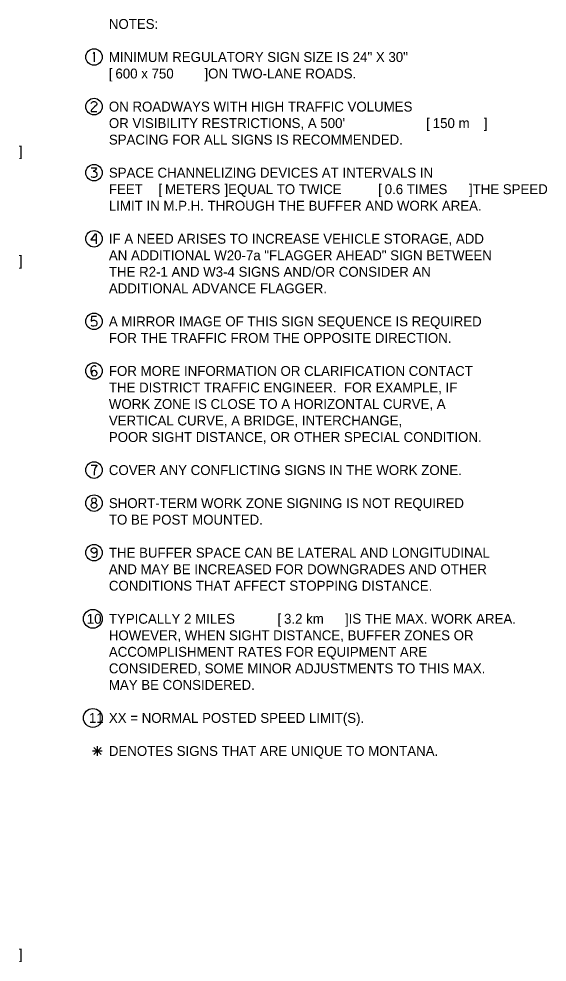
# Model space of a CAD drawing. Extents: x 49987.3 to 50021, y 49987.6 to 50011.4.
# Drawn here: x 49991.71 to 49994.9, y 50004.83 to 50010.54 of the extents above; entities that cross this region are included whole.
import ezdxf

# ---------------------------------------------------------------- set-up
doc = ezdxf.new("R2010")
doc.units = 0
doc.layers.add('Level 2', color=7, linetype='Continuous')

msp = doc.modelspace()

# ---------------------------------------------------------------- linework, layer by layer
at = {"layer": 'Level 2'}
for p, q in [((49992.1617, 50010.3362), (49992.1558, 50010.3258)), ((49992.1617, 50010.3362), (49992.1617, 50010.2762)), ((49992.1531, 50006.1064), (49992.2117, 50006.1064)), ((49992.1597, 50006.0847), (49992.2041, 50006.1282)), ((49992.2041, 50006.0847), (49992.1597, 50006.1282)), ((49992.1819, 50006.0771), (49992.1819, 50006.1357))]:
    msp.add_line(p, q, dxfattribs=at)
for points in [[(49992.1448, 50010.0241), (49992.1467, 50010.0298), (49992.1519, 50010.0345), (49992.159, 50010.0364), (49992.1642, 50010.0364), (49992.1713, 50010.0345), (49992.1765, 50010.0293), (49992.1788, 50010.0241), (49992.1788, 50010.0189), (49992.1769, 50010.0147), (49992.1651, 50010.0057), (49992.1467, 50009.9868), (49992.1448, 50009.9821), (49992.1448, 50009.9764), (49992.1788, 50009.9764)], [(49992.1448, 50009.6364), (49992.1765, 50009.6364), (49992.1746, 50009.6293), (49992.1713, 50009.6241), (49992.1665, 50009.6194), (49992.1571, 50009.6147), (49992.1642, 50009.6147), (49992.1717, 50009.6114), (49992.1765, 50009.6066), (49992.1788, 50009.5991), (49992.1788, 50009.5911), (49992.1765, 50009.583), (49992.1713, 50009.5783), (49992.1642, 50009.5764), (49992.1561, 50009.5764), (49992.1491, 50009.5783), (49992.1448, 50009.5835)], [(49992.1789, 50009.1972), (49992.1449, 50009.1972), (49992.1449, 50009.1996), (49992.1714, 50009.2364), (49992.1747, 50009.2364), (49992.1747, 50009.1764)], [(49992.1766, 50008.7364), (49992.1473, 50008.7364), (49992.1449, 50008.7081), (49992.1562, 50008.7133), (49992.1643, 50008.7133), (49992.1718, 50008.7104), (49992.1766, 50008.7052), (49992.1789, 50008.6981), (49992.1789, 50008.6906), (49992.1766, 50008.683), (49992.1718, 50008.6783), (49992.1614, 50008.6764), (49992.1543, 50008.6764), (49992.1492, 50008.6783), (49992.1449, 50008.6835)], [(49992.1753, 50008.4322), (49992.172, 50008.434), (49992.1663, 50008.4364), (49992.1607, 50008.4364), (49992.1531, 50008.434), (49992.1451, 50008.4241), (49992.1432, 50008.4147), (49992.1432, 50008.4043), (49992.1441, 50008.3953), (49992.1479, 50008.3835), (49992.1531, 50008.3783), (49992.1607, 50008.3764), (49992.173, 50008.3788), (49992.1777, 50008.3835), (49992.1805, 50008.3906), (49992.18, 50008.3944), (49992.1777, 50008.4), (49992.1725, 50008.4062), (49992.1654, 50008.4081), (49992.1602, 50008.4085), (49992.1526, 50008.4062), (49992.1479, 50008.4005), (49992.1456, 50008.3911)], [(49992.1448, 50007.8364), (49992.1788, 50007.8364), (49992.1788, 50007.834), (49992.1684, 50007.8189), (49992.1642, 50007.8071), (49992.1618, 50007.7925), (49992.1618, 50007.7764)], [(49992.1646, 50007.6095), (49992.1717, 50007.6118), (49992.1746, 50007.6147), (49992.1765, 50007.6218), (49992.1765, 50007.6246), (49992.1741, 50007.6322), (49992.1713, 50007.634), (49992.1618, 50007.6364), (49992.1519, 50007.634), (49992.1491, 50007.6322), (49992.1467, 50007.6246), (49992.1467, 50007.6218), (49992.1486, 50007.6147), (49992.1514, 50007.6118), (49992.1585, 50007.6095), (49992.1646, 50007.6095), (49992.1717, 50007.6062), (49992.1765, 50007.6005), (49992.1788, 50007.5939), (49992.1788, 50007.5915), (49992.1769, 50007.5835), (49992.1717, 50007.5783), (49992.1651, 50007.5764), (49992.1585, 50007.5764), (49992.1519, 50007.5783), (49992.1467, 50007.5835), (49992.1448, 50007.5911), (49992.1448, 50007.5939), (49992.1472, 50007.6005), (49992.1519, 50007.6062), (49992.1585, 50007.6095)], [(49992.1791, 50007.3147), (49992.1715, 50007.3071), (49992.164, 50007.3043), (49992.1592, 50007.3038), (49992.1522, 50007.3071), (49992.147, 50007.3118), (49992.1446, 50007.3194), (49992.1446, 50007.3218), (49992.1465, 50007.3298), (49992.1517, 50007.334), (49992.1592, 50007.3364), (49992.164, 50007.3364), (49992.1711, 50007.334), (49992.1767, 50007.3298), (49992.1791, 50007.3218), (49992.1791, 50007.3043), (49992.1781, 50007.2981), (49992.1763, 50007.2849), (49992.1739, 50007.2807), (49992.1711, 50007.2783), (49992.164, 50007.2764), (49992.1592, 50007.2764), (49992.1522, 50007.2783), (49992.1493, 50007.2807)]]:
    msp.add_lwpolyline(points, dxfattribs=at)
for centre, radius in [((49992.1617, 50010.3062), 0.05), ((49992.1617, 50010.0062), 0.05), ((49992.1617, 50009.6062), 0.05), ((49992.1617, 50009.2062), 0.05), ((49992.1617, 50008.7062), 0.05), ((49992.1617, 50008.4062), 0.05), ((49992.1617, 50007.8062), 0.05), ((49992.1617, 50007.6062), 0.05), ((49992.1617, 50007.3062), 0.05), ((49992.1548, 50006.9062), 0.0569), ((49992.1548, 50006.3062), 0.0569)]:
    msp.add_circle(centre, radius, dxfattribs=at)

# ---------------------------------------------------------------- texts
for s, p in [('NOTES:', (49992.2517, 50010.4762)), ('MINIMUM REGULATORY SIGN SIZE IS 24" X 30" ', (49992.2517, 50010.2762)), ('[', (49992.2517, 50010.1762)), ('600 x 750', (49992.2914, 50010.1762)), (']', (49992.8304, 50010.1762)), (' ON TWO-LANE ROADS.', (49992.83, 50010.1762)), ('ON ROADWAYS WITH HIGH TRAFFIC VOLUMES', (49992.2517, 50009.9762)), ("OR VISIBILITY RESTRICTIONS, A 500' ", (49992.2517, 50009.8762)), ('[', (49994.1717, 50009.8762)), ('150 m', (49994.2114, 50009.8762)), (']', (49994.5203, 50009.8762)), ('SPACING FOR ALL SIGNS IS RECOMMENDED.', (49992.2517, 50009.7762)), (']', (49991.7066, 50009.7065)), ('SPACE CHANNELIZING DEVICES AT INTERVALS IN ', (49992.2517, 50009.5762)), ('FEET ', (49992.2517, 50009.4762)), ('[', (49992.5517, 50009.4762)), ('METERS', (49992.5914, 50009.4762)), (']', (49992.9514, 50009.4762)), (' EQUAL TO TWICE ', (49992.9509, 50009.4762)), ('[', (49993.8809, 50009.4762)), ('0.6 TIMES', (49993.9206, 50009.4762)), (']', (49994.4306, 50009.4762)), (' THE SPEED ', (49994.4301, 50009.4762)), ('LIMIT IN M.P.H. THROUGH THE BUFFER AND WORK AREA.', (49992.2517, 50009.3762)), ('IF A NEED ARISES TO INCREASE VEHICLE STORAGE, ADD', (49992.2517, 50009.1762)), ('AN ADDITIONAL W20-7a "FLAGGER AHEAD" SIGN BETWEEN ', (49992.2517, 50009.0762)), (']', (49991.7065, 50009.0439)), ('THE R2-1 AND W3-4 SIGNS AND/OR CONSIDER AN ', (49992.2517, 50008.9762)), ('ADDITIONAL ADVANCE FLAGGER.', (49992.2517, 50008.8762)), ('A MIRROR IMAGE OF THIS SIGN SEQUENCE IS REQUIRED ', (49992.2517, 50008.6762)), ('FOR THE TRAFFIC FROM THE OPPOSITE DIRECTION.', (49992.2517, 50008.5762)), ('FOR MORE INFORMATION OR CLARIFICATION CONTACT ', (49992.2517, 50008.3762)), ('THE DISTRICT TRAFFIC ENGINEER.  FOR EXAMPLE, IF ', (49992.2517, 50008.2762)), ('WORK ZONE IS CLOSE TO A HORIZONTAL CURVE, A ', (49992.2517, 50008.1762)), ('VERTICAL CURVE, A BRIDGE, INTERCHANGE, ', (49992.2517, 50008.0762)), ('POOR SIGHT DISTANCE, OR OTHER SPECIAL CONDITION.', (49992.2517, 50007.9762)), ('COVER ANY CONFLICTING SIGNS IN THE WORK ZONE.', (49992.2517, 50007.7762)), ('SHORT-TERM WORK ZONE SIGNING IS NOT REQUIRED ', (49992.2517, 50007.5762)), ('TO BE POST MOUNTED.', (49992.2517, 50007.4762)), ('THE BUFFER SPACE CAN BE LATERAL AND LONGITUDINAL', (49992.2517, 50007.2762)), ('AND MAY BE INCREASED FOR DOWNGRADES AND OTHER', (49992.2517, 50007.1762)), ('CONDITIONS THAT AFFECT STOPPING DISTANCE.', (49992.2517, 50007.0762)), ('10', (49992.118, 50006.8762)), ('TYPICALLY 2 MILES ', (49992.2517, 50006.8762)), ('[', (49993.2717, 50006.8762)), ('3.2 km', (49993.3114, 50006.8762)), (']', (49993.6808, 50006.8762)), (' IS THE MAX. WORK AREA.  ', (49993.6803, 50006.8762)), ('HOWEVER, WHEN SIGHT DISTANCE, BUFFER ZONES OR ', (49992.2517, 50006.7762)), ('ACCOMPLISHMENT RATES FOR EQUIPMENT ARE ', (49992.2517, 50006.6762)), ('CONSIDERED, SOME MINOR ADJUSTMENTS TO THIS MAX.', (49992.2517, 50006.5762)), ('MAY BE CONSIDERED.', (49992.2517, 50006.4762)), ('11', (49992.1308, 50006.2762)), ('XX = NORMAL POSTED SPEED LIMIT(S).', (49992.2517, 50006.2762)), ('DENOTES SIGNS THAT ARE UNIQUE TO MONTANA.', (49992.2517, 50006.0762)), (']', (49991.7065, 50004.8464))]:
    msp.add_text(s, height=0.06, dxfattribs=at).set_placement(p)

doc.saveas('drawing.dxf')
